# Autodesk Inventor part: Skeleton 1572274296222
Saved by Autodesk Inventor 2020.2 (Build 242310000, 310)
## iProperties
Part Number: Skeleton 1572274296222
Material: Allgemein
Document SubType Name: Modellieren
Designer: lutzd
Density: 1 g/cm^3
Appearance: Vorgabe
Mass: 0 kg
VLT_Material: Generisch
Dimensions: 0x0x0 mm
_SkeletonDoc: Frame Skeleton File
_Version: 15.0.0
Author: lutzd
Revision Number: -
Title: Skeleton 1572274296222
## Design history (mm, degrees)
sketch "Referenzrahmen"
node "Volumenkörper"
node "Flächenkörper"
